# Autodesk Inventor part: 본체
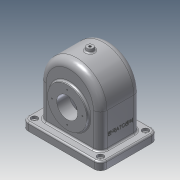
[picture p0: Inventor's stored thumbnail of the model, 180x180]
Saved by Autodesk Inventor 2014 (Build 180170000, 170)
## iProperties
Created: 2016-10
Part Number: 본체
Material: 알루미늄 6061
Document SubType Name: Modeling
Designer: 703-17
Density: 2.71 g/cm^3
Appearance: 알루미늄 - 평지
Mass: 1165.4 g
Surface Area: 1201.5 cm^2
Volume: 430.035 cm^3
Author: 703-17
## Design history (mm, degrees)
sketch "스케치2"
  geometry: L1 (-55, 75)-(55, 75); L2 (55, 75)-(55, -75); L3 (55, -75)-(-55, -75); L4 (-55, -75)-(-55, 75); L5 (-55, 75)-(55, -75); L6 (55, 75)-(-55, -75); 1 further point
  constraints: 12 end point, 2 midpoint, 2 parallel, 1 horizontal, 1 perpendicular
  dimensions: "d2" = 150 distance between parallel lines of L3 L1; "d3" = 110 distance between parallel lines of L2 L4
extrude "돌출1" new body sketch "스케치2" distance "d4" = 15; taper "d5" = 0 deg
fillet "모깎기1" dims "d6" = 12
sketch "스케치3"
  geometry: L1 (-38.5, -58)-(38.5, -58); L2 (38.5, -58)-(38.5, 58); L3 (38.5, 58)-(-38.5, 58); L4 (-38.5, 58)-(-38.5, -58); L5 (-38.5, -58)-(38.5, 58); L6 (38.5, -58)-(-38.5, 58); 3 further points
  constraints: 12 end point, 3 midpoint, 2 parallel, 1 coincident, 1 horizontal, 1 perpendicular
  dimensions: "d7" = 77 distance between parallel lines of L4 L2; "d57" = 116 distance between parallel lines of L1 L3
extrude "돌출2" join sketch "스케치3" distance "d10" = 65; taper "d11" = 0 deg
sketch "스케치4"
  geometry: L1 (-38.5, 58)-(-38.5, -58) reference; L2 (-38.5, 0)-(38.5, 0); L3 (38.5, 0)-(38.5, 58); L4 (38.5, 58)-(-38.5, 58); L5 (-38.5, 58)-(-38.5, 0); 1 further point
  constraints: 8 end point, 2 parallel, 1 horizontal, 1 midpoint, 1 perpendicular
revolve "회전1" sketch "스케치4" stored, may be unused: angle "d12" = 180 deg
sketch "스케치5"
  geometry: L1 (0, 0)-(-65, 0); L2 (15, 121)-(15, -5) reference; C1 r 31 at (-50, 58); A1 r 59.908 centre (-50, 58) between (-65, 116) and (-65, 0); 1 further point
  constraints: 2 centre point, 2 end point, 2 point on circle, 1 coincident
  dimensions: "d13" = 62 diameter of C1; "d86" = 65 distance from line of L2 A1.centre
extrude "돌출3" join sketch "스케치5" distance "d14" = 10; taper "d15" = 0 deg
sketch "스케치6"
  geometry: L1 (0, 0)-(0, 116); L2 (0, 0)-(65, 0); L3 (0, 116)-(65, 116); L4 (-15, -5)-(-15, 121) reference; C1 r 37.5 at (50, 58); A1 r 59.908 centre (50, 58) between (65, 0) and (65, 116); 1 further point
  constraints: 6 end point, 2 centre point, 2 point on circle, 1 coincident
  dimensions: "d16" = 75 diameter of C1; "d87" = 65 distance from line of L4 A1.centre
extrude "돌출4" join sketch "스케치6" distance "d17" = 5; taper "d18" = 0 deg
sketch "스케치8"
  geometry: L1 (-33.5, -52)-(33.5, -52); L2 (33.5, -52)-(33.5, 52); L3 (33.5, 52)-(-33.5, 52); L4 (-33.5, 52)-(-33.5, -52); L5 (-33.5, -52)-(33.5, 52); L6 (33.5, -52)-(-33.5, 52); L7 (-38.5, 58)-(38.5, 58) reference; L8 (38.5, -58)-(38.5, 58) reference; 1 further point
  constraints: 12 end point, 2 midpoint, 2 parallel, 1 horizontal, 1 perpendicular
  dimensions: "d19" = 6 distance between parallel lines of L7 L3; "d20" = 5 distance between parallel lines of L8 L2
extrude "돌출5" cut sketch "스케치8" distance "d21" = 80; taper "d22" = 0 deg
sketch "스케치9"
  geometry: L1 (-33.5, -52)-(-33.5, 52) reference; L2 (-33.5, 0)-(33.5, 0); L3 (33.5, 0)-(33.5, 52); L4 (33.5, 52)-(-33.5, 52); L5 (-33.5, 52)-(-33.5, 0); 1 further point
  constraints: 8 end point, 2 parallel, 1 horizontal, 1 midpoint, 1 perpendicular
revolve "회전2" sketch "스케치9" stored, may be unused: angle "d23" = 180 deg
sketch "스케치10"
  geometry: L1 (36.521, 107.282)-(19.5, 93); L2 (19.5, 93)-(19.5, 65); L3 (19.5, 65)-(36.521, 65); L4 (36.521, 65)-(36.521, 107.282); L5 (43.5, 27.5)-(43.5, 102.5) reference; L6 (43, 0)-(-43, 0) reference; 1 further point
  constraints: 8 end point, 2 perpendicular, 1 vertical
  dimensions: "d24" = 50 deg angle of L2 L1; "d25" = 24 distance between parallel lines of L5 L2; "d26" = 56 diameter of L1.end L3; "d88" = 65 distance between parallel lines of L6 L3
revolve "회전3" sketch "스케치10" stored, may be unused: angle "d27" = 180 deg
sketch "스케치12"
  geometry: C1 r 31 at (0, 0) reference; 1 further point
hole "구멍1" sketch "스케치12" at (0, 0) diameter "d28" = 40; stored, may be unused: countersink angle "d32" = 90 deg, drill point angle "d34" = 118 deg; dims "d29" = 6, "d30" = 4, "d31" = 2, "d33" = 8
sketch "스케치15"
  geometry: L1 (0, 144)-(6, 144); L2 (6, 144)-(7.825, 133.651); L3 (7.825, 133.651)-(0, 133.651); L4 (0, 133.651)-(0, 144); L5 (43, 0)-(-43, 0) reference; 3 further points
  constraints: 8 end point, 2 midpoint, 1 horizontal, 1 parallel, 1 perpendicular, 1 vertical alignment
  dimensions: "d37" = 100 deg angle of L2 L3; "d39" = 12 diameter of L1.end L4; "d40" = 144 distance between parallel lines of L1 L5
revolve "회전4" sketch "스케치15" stored, may be unused: angle "d41" = 180 deg
sketch "스케치16"
  geometry: C1 r 6 at (0, 0) reference
hole "구멍2" sketch "스케치16" at (0, 0) diameter "d42" = 4.459; stored, may be unused: countersink angle "d46" = 90 deg, drill point angle "d48" = 118 deg; dims "d43" = 20, "d44" = 4, "d45" = 2, "d47" = 8
sketch "스케치17"
  geometry: A1 r 12 centre (-43, 63) between (-43, 75) and (-55, 63) reference; A2 r 12 centre (-43, -63) between (-55, -63) and (-43, -75) reference; A3 r 12 centre (43, -63) between (43, -75) and (55, -63) reference; A4 r 12 centre (43, 63) between (55, 63) and (43, 75) reference; 1 further point
hole "구멍3" sketch "스케치17" at (-43, -63), (-43, 63), (43, 63), (43, -63) diameter "d49" = 5; stored, may be unused: countersink angle "d53" = 90 deg, drill point angle "d55" = 118 deg; dims "d50" = 5, "d51" = 12, "d52" = 5, "d54" = 8
fillet "모깎기3" dims "d58" = 13
fillet "모깎기4" dims "d59" = 3
fillet "모깎기5" dims "d60" = 8
fillet "모깎기6" dims "d61" = 3
sketch "스케치18" dims "d62" = 58
  geometry: C1 r 37.5 at (0, 0) reference; 3 further points
  constraints: 1 coincident, 1 horizontal alignment, 2 other
hole "구멍4" sketch "스케치18" at (29, 0) diameter "d63" = 2.459; stored, may be unused: countersink angle "d67" = 90 deg, drill point angle "d69" = 118 deg; dims "d64" = 6, "d65" = 12, "d66" = 5, "d68" = 8
sketch "스케치19" dims "d73" = 52
  geometry: C1 r 31 at (0, 0) reference; 3 further points
  constraints: 1 coincident, 1 horizontal alignment, 2 other
hole "구멍5" sketch "스케치19" at (-26, 0) diameter "d74" = 2.459; stored, may be unused: countersink angle "d78" = 90 deg, drill point angle "d80" = 118 deg; dims "d75" = 6, "d76" = 12, "d77" = 5, "d79" = 8
sketch "스케치20" dims "d2" = 150, "d3" = 110
  geometry: L1 (68.5, -80)-(-17.5, -80) reference; L2 (-13, 0)-(-13, -62) reference; 2 further points
  constraints: 1 other
  dimensions: "d84" = 40 distance from line of L1 point (25.5, -40); "d85" = 38.5 distance from line of point (25.5, -40) L2
feature "엠보싱1" sketch "스케치20" dims "d2" = 150, "d3" = 110, "d60" = 8, "d89" = 0.5, "d90" = 0
node "솔리드1"
pattern_circular "원형 패턴1" dims angle "d71" = 360 deg
pattern_circular "원형 패턴2" dims angle "d82" = 360 deg
